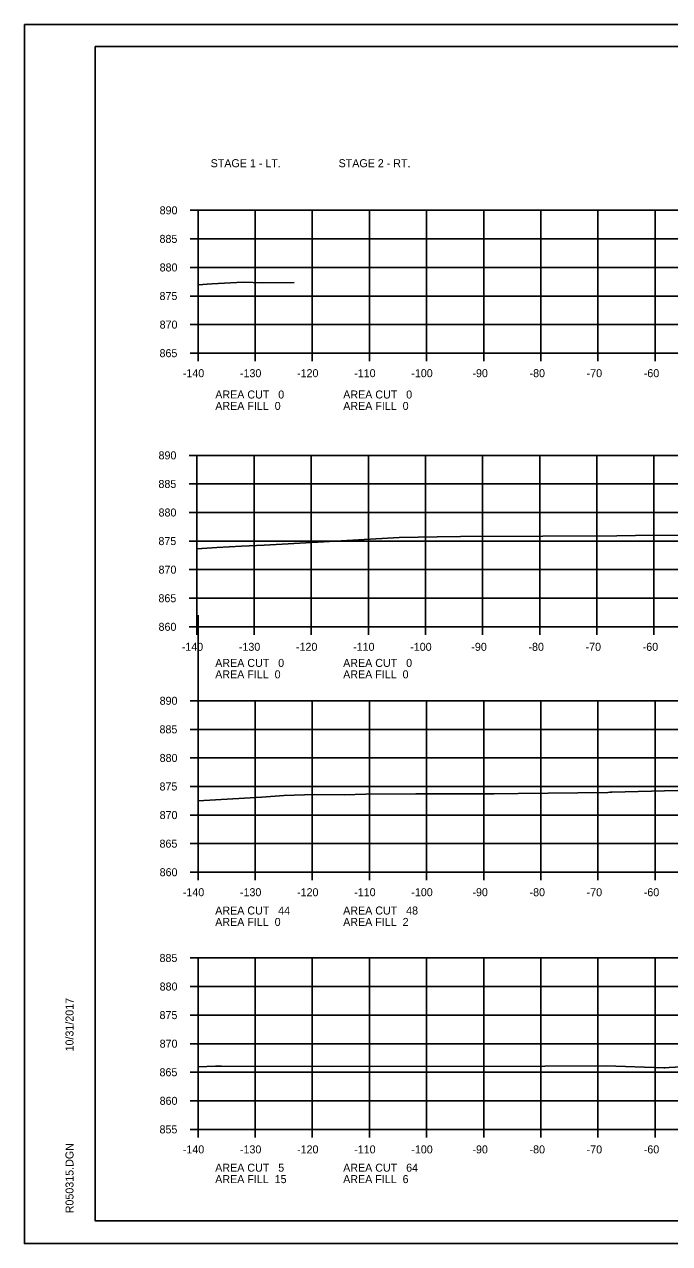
# Model space of a CAD drawing. Extents: x 1486524 to 1499135, y 326561 to 337924.
# Drawn here: x 1488812.5 to 1488925.4, y 336192.7 to 336406.1 of the extents above; entities that cross this region are included whole.
import ezdxf

# ---------------------------------------------------------------- set-up
doc = ezdxf.new("R2010")
doc.units = 0
for name, color, linetype in [('Default', 7, 'Continuous'), ('E_Const Align', 7, 'Continuous'), ('E_Const Align Station', 7, 'Continuous'), ('E_Ownership Information', 7, 'Continuous'), ('E_Property Line', 7, 'Continuous'), ('E_Proposed ROW and Easements', 7, 'Continuous'), ('E_Quarter Calls', 7, 'Continuous'), ('E_Tract Number', 7, 'Continuous')]:
    doc.layers.add(name, color=color, linetype=linetype)

msp = doc.modelspace()

# ---------------------------------------------------------------- linework, layer by layer
at = {"layer": 'E_Const Align'}
for p, q in [((1488841.49, 336373.52), (1488842.89, 336373.52)), ((1488842.89, 336348.52), (1488842.89, 336373.52)), ((1488841.49, 336368.52), (1488842.89, 336368.52)), ((1488841.49, 336363.52), (1488842.89, 336363.52)), ((1488841.49, 336358.52), (1488842.89, 336358.52)), ((1488841.49, 336353.52), (1488842.89, 336353.52)), ((1488841.49, 336348.52), (1488842.89, 336348.52)), ((1488842.89, 336348.52), (1489122.89, 336348.52)), ((1488842.89, 336347.12), (1488842.89, 336348.52)), ((1488852.89, 336347.12), (1488852.89, 336348.52)), ((1488862.89, 336347.12), (1488862.89, 336348.52)), ((1488872.89, 336347.12), (1488872.89, 336348.52)), ((1488882.89, 336347.12), (1488882.89, 336348.52)), ((1488892.89, 336347.12), (1488892.89, 336348.52)), ((1488902.89, 336347.12), (1488902.89, 336348.52)), ((1488912.89, 336347.12), (1488912.89, 336348.52)), ((1488922.89, 336347.12), (1488922.89, 336348.52)), ((1488841.3, 336330.64), (1488842.7, 336330.64)), ((1488842.7, 336300.64), (1488842.7, 336330.64)), ((1488841.3, 336325.64), (1488842.7, 336325.64)), ((1488841.3, 336320.64), (1488842.7, 336320.64)), ((1488841.3, 336315.64), (1488842.7, 336315.64)), ((1488841.3, 336310.64), (1488842.7, 336310.64)), ((1488841.3, 336305.64), (1488842.7, 336305.64)), ((1488841.3, 336300.64), (1488842.7, 336300.64)), ((1488842.7, 336300.64), (1489122.7, 336300.64)), ((1488842.7, 336299.24), (1488842.7, 336300.64)), ((1488852.7, 336299.24), (1488852.7, 336300.64)), ((1488862.7, 336299.24), (1488862.7, 336300.64)), ((1488872.7, 336299.24), (1488872.7, 336300.64)), ((1488882.7, 336299.24), (1488882.7, 336300.64)), ((1488892.7, 336299.24), (1488892.7, 336300.64)), ((1488902.7, 336299.24), (1488902.7, 336300.64)), ((1488912.7, 336299.24), (1488912.7, 336300.64)), ((1488922.7, 336299.24), (1488922.7, 336300.64)), ((1488841.49, 336287.7), (1488842.89, 336287.7)), ((1488842.89, 336257.7), (1488842.89, 336287.7)), ((1488841.49, 336282.7), (1488842.89, 336282.7)), ((1488841.49, 336277.7), (1488842.89, 336277.7)), ((1488841.49, 336272.7), (1488842.89, 336272.7)), ((1488841.49, 336267.7), (1488842.89, 336267.7)), ((1488841.49, 336262.7), (1488842.89, 336262.7)), ((1488841.49, 336257.7), (1488842.89, 336257.7)), ((1488842.89, 336257.7), (1489122.89, 336257.7)), ((1488842.89, 336256.3), (1488842.89, 336257.7)), ((1488852.89, 336256.3), (1488852.89, 336257.7)), ((1488862.89, 336256.3), (1488862.89, 336257.7)), ((1488872.89, 336256.3), (1488872.89, 336257.7)), ((1488882.89, 336256.3), (1488882.89, 336257.7)), ((1488892.89, 336256.3), (1488892.89, 336257.7)), ((1488902.89, 336256.3), (1488902.89, 336257.7)), ((1488912.89, 336256.3), (1488912.89, 336257.7)), ((1488922.89, 336256.3), (1488922.89, 336257.7)), ((1488841.49, 336242.7), (1488842.89, 336242.7)), ((1488842.89, 336212.7), (1488842.89, 336242.7)), ((1488841.49, 336237.7), (1488842.89, 336237.7)), ((1488841.49, 336232.7), (1488842.89, 336232.7)), ((1488841.49, 336227.7), (1488842.89, 336227.7)), ((1488841.49, 336222.7), (1488842.89, 336222.7)), ((1488841.49, 336217.7), (1488842.89, 336217.7)), ((1488841.49, 336212.7), (1488842.89, 336212.7)), ((1488842.89, 336212.7), (1489122.89, 336212.7)), ((1488842.89, 336211.3), (1488842.89, 336212.7)), ((1488852.89, 336211.3), (1488852.89, 336212.7)), ((1488862.89, 336211.3), (1488862.89, 336212.7)), ((1488872.89, 336211.3), (1488872.89, 336212.7)), ((1488882.89, 336211.3), (1488882.89, 336212.7)), ((1488892.89, 336211.3), (1488892.89, 336212.7)), ((1488902.89, 336211.3), (1488902.89, 336212.7)), ((1488912.89, 336211.3), (1488912.89, 336212.7)), ((1488922.89, 336211.3), (1488922.89, 336212.7))]:
    msp.add_line(p, q, dxfattribs=at)
at = {"layer": 'E_Ownership Information'}
for p, q in [((1488842.89, 336373.52), (1489122.89, 336373.52)), ((1488842.89, 336348.52), (1488842.89, 336373.52)), ((1488842.89, 336373.52), (1489122.89, 336373.52)), ((1488842.89, 336348.52), (1488842.89, 336373.52)), ((1488852.89, 336348.52), (1488852.89, 336373.52)), ((1488852.89, 336348.52), (1488852.89, 336373.52)), ((1488862.89, 336348.52), (1488862.89, 336373.52)), ((1488862.89, 336348.52), (1488862.89, 336373.52)), ((1488872.89, 336348.52), (1488872.89, 336373.52)), ((1488872.89, 336348.52), (1488872.89, 336373.52)), ((1488882.89, 336348.52), (1488882.89, 336373.52)), ((1488882.89, 336348.52), (1488882.89, 336373.52)), ((1488892.89, 336348.52), (1488892.89, 336373.52)), ((1488892.89, 336348.52), (1488892.89, 336373.52)), ((1488902.89, 336348.52), (1488902.89, 336373.52)), ((1488902.89, 336348.52), (1488902.89, 336373.52)), ((1488912.89, 336348.52), (1488912.89, 336373.52)), ((1488912.89, 336348.52), (1488912.89, 336373.52)), ((1488922.89, 336348.52), (1488922.89, 336373.52)), ((1488922.89, 336348.52), (1488922.89, 336373.52)), ((1488842.89, 336368.52), (1489122.89, 336368.52)), ((1488842.89, 336368.52), (1489122.89, 336368.52)), ((1488842.89, 336363.52), (1489122.89, 336363.52)), ((1488842.89, 336363.52), (1489122.89, 336363.52)), ((1488842.89, 336358.52), (1489122.89, 336358.52)), ((1488842.89, 336358.52), (1489122.89, 336358.52)), ((1488842.89, 336353.52), (1489122.89, 336353.52)), ((1488842.89, 336353.52), (1489122.89, 336353.52)), ((1488842.89, 336348.52), (1489122.89, 336348.52)), ((1488842.89, 336348.52), (1489122.89, 336348.52)), ((1488842.7, 336330.64), (1489122.7, 336330.64)), ((1488842.7, 336300.64), (1488842.7, 336330.64)), ((1488852.7, 336300.64), (1488852.7, 336330.64)), ((1488862.7, 336300.64), (1488862.7, 336330.64)), ((1488872.7, 336300.64), (1488872.7, 336330.64)), ((1488882.7, 336300.64), (1488882.7, 336330.64)), ((1488892.7, 336300.64), (1488892.7, 336330.64)), ((1488902.7, 336300.64), (1488902.7, 336330.64)), ((1488912.7, 336300.64), (1488912.7, 336330.64)), ((1488922.7, 336300.64), (1488922.7, 336330.64)), ((1488842.7, 336325.64), (1489122.7, 336325.64)), ((1488842.7, 336320.64), (1489122.7, 336320.64)), ((1488842.7, 336315.64), (1489122.7, 336315.64)), ((1488842.7, 336310.64), (1489122.7, 336310.64)), ((1488842.7, 336305.64), (1489122.7, 336305.64)), ((1488842.7, 336300.64), (1489122.7, 336300.64)), ((1488842.89, 336287.7), (1489122.89, 336287.7)), ((1488842.89, 336257.7), (1488842.89, 336287.7)), ((1488852.89, 336257.7), (1488852.89, 336287.7)), ((1488862.89, 336257.7), (1488862.89, 336287.7)), ((1488872.89, 336257.7), (1488872.89, 336287.7)), ((1488882.89, 336257.7), (1488882.89, 336287.7)), ((1488892.89, 336257.7), (1488892.89, 336287.7)), ((1488902.89, 336257.7), (1488902.89, 336287.7)), ((1488912.89, 336257.7), (1488912.89, 336287.7)), ((1488922.89, 336257.7), (1488922.89, 336287.7)), ((1488842.89, 336282.7), (1489122.89, 336282.7)), ((1488842.89, 336277.7), (1489122.89, 336277.7)), ((1488842.89, 336272.7), (1489122.89, 336272.7)), ((1488842.89, 336267.7), (1489122.89, 336267.7)), ((1488842.89, 336262.7), (1489122.89, 336262.7)), ((1488842.89, 336257.7), (1489122.89, 336257.7)), ((1488842.89, 336242.7), (1489122.89, 336242.7)), ((1488842.89, 336212.7), (1488842.89, 336242.7)), ((1488852.89, 336212.7), (1488852.89, 336242.7)), ((1488862.89, 336212.7), (1488862.89, 336242.7)), ((1488872.89, 336212.7), (1488872.89, 336242.7)), ((1488882.89, 336212.7), (1488882.89, 336242.7)), ((1488892.89, 336212.7), (1488892.89, 336242.7)), ((1488902.89, 336212.7), (1488902.89, 336242.7)), ((1488912.89, 336212.7), (1488912.89, 336242.7)), ((1488922.89, 336212.7), (1488922.89, 336242.7)), ((1488842.89, 336237.7), (1489122.89, 336237.7)), ((1488842.89, 336232.7), (1489122.89, 336232.7)), ((1488842.89, 336227.7), (1489122.89, 336227.7)), ((1488842.89, 336222.7), (1489122.89, 336222.7)), ((1488842.89, 336217.7), (1489122.89, 336217.7)), ((1488842.89, 336212.7), (1489122.89, 336212.7))]:
    msp.add_line(p, q, dxfattribs=at)
at = {"layer": 'E_Property Line'}
for p, q in [((1488824.89, 336402.16), (1489141.07, 336402.16)), ((1488824.89, 336196.7), (1488824.89, 336402.16)), ((1488824.89, 336196.7), (1488824.89, 336196.7)), ((1489141.07, 336196.7), (1488824.89, 336196.7))]:
    msp.add_line(p, q, dxfattribs=at)
at = {"layer": 'E_Proposed ROW and Easements'}
msp.add_line((1488842.89, 336287.7), (1488842.89, 336302.7), dxfattribs=at)
at = {"layer": 'E_Quarter Calls'}
for p, q in [((1488812.48, 336406.05), (1489145.82, 336406.05)), ((1488812.48, 336192.72), (1489145.82, 336192.72))]:
    msp.add_line(p, q, dxfattribs=at)
for points in [[(1488812.48, 336406.05), (1489145.82, 336406.05), (1489145.82, 336192.71), (1488812.48, 336192.71)], [(1489058.81, 336402.16), (1489058.81, 336392.28), (1489094.54, 336392.28), (1489094.54, 336389.36), (1489117.74, 336389.36), (1489117.74, 336365.02), (1489141.07, 336365.02), (1489141.07, 336196.7), (1488824.89, 336196.7), (1488824.89, 336402.16)]]:
    msp.add_lwpolyline(points, close=True, dxfattribs=at)
at = {"layer": 'E_Tract Number'}
for points in [[(1488842.89, 336360.47), (1488845.29, 336360.63), (1488850.77, 336360.95), (1488854.24, 336360.83), (1488859.7, 336360.89)], [(1488842.7, 336314.3), (1488846.19, 336314.49), (1488850.52, 336314.75), (1488854.48, 336314.92), (1488863.88, 336315.46), (1488878.11, 336316.28), (1488884.75, 336316.4), (1488888.82, 336316.44), (1488903.22, 336316.48), (1488916.22, 336316.57), (1488919.49, 336316.59), (1488927.52, 336316.65)], [(1488842.89, 336270.21), (1488854.04, 336270.84), (1488857.93, 336271.12), (1488863.34, 336271.3), (1488868.45, 336271.26), (1488872.24, 336271.35), (1488880.99, 336271.4), (1488894.72, 336271.44), (1488898.92, 336271.49), (1488914.63, 336271.66), (1488915.06, 336271.68), (1488915.16, 336271.68), (1488915.32, 336271.68), (1488931.49, 336272.09)], [(1488842.89, 336223.64), (1488845.95, 336223.74), (1488846.71, 336223.74), (1488847, 336223.75), (1488866.33, 336223.73), (1488903.61, 336223.77), (1488914.35, 336223.84), (1488924.42, 336223.5), (1488924.61, 336223.49), (1488925.34, 336223.52), (1488941.84, 336224.48)]]:
    msp.add_lwpolyline(points, dxfattribs=at)

# ---------------------------------------------------------------- texts
at = {"layer": 'Default'}
for s, p in [('STAGE 1 - LT.', (1488845.09, 336381.06)), ('STAGE 2 - RT.', (1488867.49, 336381.06))]:
    msp.add_text(s, height=1.4, dxfattribs=at).set_placement(p)
at = {"layer": 'E_Const Align Station'}
for s, p in [('890', (1488836.16, 336372.82)), ('885', (1488836.14, 336367.82)), ('880', (1488836.16, 336362.82)), ('875', (1488836.14, 336357.82)), ('870', (1488836.16, 336352.82)), ('865', (1488836.14, 336347.82)), ('-140', (1488840.22, 336344.32)), ('-130', (1488850.22, 336344.32)), ('-120', (1488860.22, 336344.32)), ('-110', (1488870.22, 336344.32)), ('-100', (1488880.22, 336344.32)), ('-90', (1488890.92, 336344.32)), ('-80', (1488900.92, 336344.32)), ('-70', (1488910.92, 336344.32)), ('-60', (1488920.92, 336344.32)), ('AREA CUT   0', (1488845.9, 336340.59)), ('AREA CUT   0', (1488868.3, 336340.59)), ('AREA FILL  0', (1488845.9, 336338.59)), ('AREA FILL  0', (1488868.3, 336338.59)), ('890', (1488835.97, 336329.94)), ('885', (1488835.95, 336324.94)), ('880', (1488835.97, 336319.94)), ('875', (1488835.95, 336314.94)), ('870', (1488835.97, 336309.94)), ('865', (1488835.95, 336304.94)), ('860', (1488835.97, 336299.94)), ('-140', (1488840.03, 336296.44)), ('-130', (1488850.03, 336296.44)), ('-120', (1488860.03, 336296.44)), ('-110', (1488870.03, 336296.44)), ('-100', (1488880.03, 336296.44)), ('-90', (1488890.73, 336296.44)), ('-80', (1488900.73, 336296.44)), ('-70', (1488910.73, 336296.44)), ('-60', (1488920.73, 336296.44)), ('AREA CUT   0', (1488845.89, 336293.62)), ('AREA CUT   0', (1488868.29, 336293.62)), ('AREA FILL  0', (1488845.89, 336291.62)), ('AREA FILL  0', (1488868.29, 336291.62)), ('890', (1488836.16, 336287)), ('885', (1488836.14, 336282)), ('880', (1488836.16, 336277)), ('875', (1488836.14, 336272)), ('870', (1488836.16, 336267)), ('865', (1488836.14, 336262)), ('860', (1488836.16, 336257)), ('-140', (1488840.22, 336253.5)), ('-130', (1488850.22, 336253.5)), ('-120', (1488860.22, 336253.5)), ('-110', (1488870.22, 336253.5)), ('-100', (1488880.22, 336253.5)), ('-90', (1488890.92, 336253.5)), ('-80', (1488900.92, 336253.5)), ('-70', (1488910.92, 336253.5)), ('-60', (1488920.92, 336253.5)), ('AREA CUT   44', (1488845.89, 336250.3)), ('AREA CUT   48', (1488868.29, 336250.3)), ('AREA FILL  0', (1488845.89, 336248.3)), ('AREA FILL  2', (1488868.29, 336248.3)), ('885', (1488836.14, 336242)), ('880', (1488836.16, 336237)), ('875', (1488836.14, 336232)), ('870', (1488836.16, 336227)), ('865', (1488836.14, 336222)), ('860', (1488836.16, 336217)), ('855', (1488836.14, 336212)), ('-140', (1488840.22, 336208.5)), ('-130', (1488850.22, 336208.5)), ('-120', (1488860.22, 336208.5)), ('-110', (1488870.22, 336208.5)), ('-100', (1488880.22, 336208.5)), ('-90', (1488890.92, 336208.5)), ('-80', (1488900.92, 336208.5)), ('-70', (1488910.92, 336208.5)), ('-60', (1488920.92, 336208.5)), ('AREA CUT   5', (1488845.89, 336205.3)), ('AREA CUT   64', (1488868.29, 336205.3)), ('AREA FILL  15', (1488845.89, 336203.3)), ('AREA FILL  6', (1488868.29, 336203.3))]:
    msp.add_text(s, height=1.4, dxfattribs=at).set_placement(p)
at = {"layer": 'E_Property Line'}
for s, p in [('10/31/2017', (1488821.08, 336226.34)), ('R050315.DGN', (1488821.08, 336198.02))]:
    msp.add_text(s, height=1.4, rotation=90, dxfattribs=at).set_placement(p)

doc.saveas('drawing.dxf')
